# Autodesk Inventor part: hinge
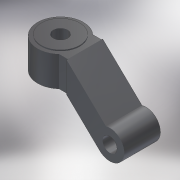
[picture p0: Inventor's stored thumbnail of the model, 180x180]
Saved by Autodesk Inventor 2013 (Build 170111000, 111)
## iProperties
Shininess: 69.0
Length Units: 11269
Angle Units: 11279
Time Units: 11290
Mass Units: 11283
Length Display Precision: 3
Angle Display Precision: 2
Created: 2002-03
Part Number: hinge
Material: UHMW, Black
Document SubType Name: Modeling
Designer: =<Author>
Density: 0.94 g/cm^3
Description: =<Part Number>
Density: 0.94
Volumn: 7.049523290984103
Area: 31.649047990386027
PropertySet Name: Model Information
Control State: 0
Master: False
Checked Out: True
Last Check In Date: 2008-10-15
Checked Out Date: 2008-10-15
Author: LAlexey
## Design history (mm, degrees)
sketch "Sketch1"
  geometry: L1 (0.917, 15.401)-(4.495, 15.401); L2 (4.495, 15.401)-(4.495, 1.401); L3 (4.495, 1.401)-(0.917, 1.401); C1 r 3 at (-5.505, 8.401); A1 r 9.5 centre (-5.505, 8.401) between (0.917, 15.401) and (0.917, 1.401)
  constraints: 6 end point, 2 centre point, 2 parallel, 2 point on circle, 1 coincident, 1 horizontal, 1 perpendicular
  dimensions: "d0" = 19 diameter of A1; "d1" = 6 diameter of C1; "d4" = 10 distance from line of L2 A1.centre; "d5" = 14 distance between parallel lines of L3 L1
extrude "Extrusion1" new body sketch "Sketch1" distance "d2" = 12.5; taper "d3" = 0 deg
sketch "Sketch2"
  geometry: C1 r 3 at (-5.505, 8.401) reference; C2 r 8 at (-5.505, 8.401); A1 r 9.5 centre (-5.505, 8.401) between (0.917, 15.401) and (0.917, 1.401) reference
  constraints: 1 centre point, 1 coincident
  dimensions: "d6" = 16 diameter of C2
extrude "Extrusion2" join sketch "Sketch2" distance "d7" = 0.5; taper "d8" = 0 deg
workaxis "Work Axis1"
workplane "Work Plane1"
sketch "Sketch3"
  geometry: L1 (-6.423, 0)-(-10, 0) reference; L2 (-6.423, 12.5)-(-10, 12.5) reference; L3 (-10, 0)-(-23.839, -13.322); L4 (-10, 12.5)-(-26.343, -3.233); L5 (0, -22.122)-(0, 18.854) reference; L6 (-8, 13)-(8, 13) reference; L7 (-10, 0)-(-10, 12.5); C1 r 3 at (-28, -9); A1 r 6 centre (-28, -9) between (-26.343, -3.233) and (-23.839, -13.322)
  constraints: 6 end point, 2 centre point, 2 point on circle, 1 coincident, 1 parallel, 1 perpendicular, 1 tangent
  dimensions: "d11" = 28 distance from line of A1.centre L5; "d12" = 22 distance from line of A1.centre L6; "d13" = 6 radius of A1; "d14" = 6 diameter of C1
extrude "Extrusion3" join sketch "Sketch3" stored distance "d15" = 15; taper "d16" = 0 deg
body "Solid1"
other parameters: "d9" = 90 deg, "d10" = 90 deg
